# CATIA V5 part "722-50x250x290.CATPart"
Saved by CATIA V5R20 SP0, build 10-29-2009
Part number: 722-50x250x290
Definition: NONE
Nomenclature: 722-50x250x290
Source: Unknown
Description: 722-50x250x290
Bounding box of the stored display mesh (mm): x -25 to 25, y -24.818 to 24.818, z -232 to 58
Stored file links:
  C:\Users\Utente\Desktop\IO LAVORO\3D X SITO CF\X SITO\722\722-50x250x290.CATPart
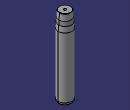
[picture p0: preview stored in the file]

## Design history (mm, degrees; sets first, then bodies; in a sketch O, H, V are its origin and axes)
Body1 "722-50x250x290" (main body)
  Solid1: solid without history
